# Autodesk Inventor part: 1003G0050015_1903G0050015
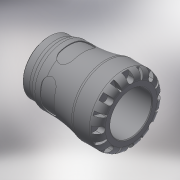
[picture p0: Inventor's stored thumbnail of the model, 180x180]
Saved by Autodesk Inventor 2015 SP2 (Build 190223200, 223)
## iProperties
Created: 2016-12
Part Number: 1003G0050015_1903G0050015
Material: Generic
Description: PLASSON FEMALE ADAPTOR 50x1 1/2" SERIES 1
Document SubType Name: Modeling
Designer: KIM
Mass: 295.885 g
Surface Area: 511.44 cm^2
Volume: 295.885 cm^3
Density: 1 g/cm^3
Appearance: Default
Author: KIM
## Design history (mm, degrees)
derived "1003G.ipt"
feature "Solid1::1003G.ipt"
tag "TaggingFeature1"
body "Solid1"
other parameters: "d1" = 32.76, "d3" = 62.5, "d4" = 85, "d6" = 78, "d8" = 72.25, "d13" = 9, "d14" = 9, "d15" = 0, "d17" = 360 deg, "d19" = 8 deg, "d20" = 1, "d21" = 1, "d22" = 8 deg, "d24" = 0, "d26" = 360 deg, "d32" = 8.5, "d33" = 8.5, "d39" = 1.34535, "d42" = 44.845, "d43" = 66.3, "d46" = 4.16667, "d47" = 19, "d48" = 42.60275, "d50" = 4.29, "d51" = 0.85, "d54" = 17.5, "d55" = 11, "d57" = 17.64, "d58" = 0, "d68" = 360 deg, "d72" = 1, "d74" = 0, "d76" = 14.875, "E_" = 85, "l_" = 78, "G_" = 44.845, "l_2" = 19, "d9" = 11.25, "d11" = 85, "d12" = 62.5, "d49" = 13
